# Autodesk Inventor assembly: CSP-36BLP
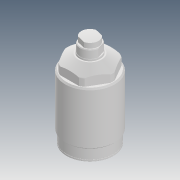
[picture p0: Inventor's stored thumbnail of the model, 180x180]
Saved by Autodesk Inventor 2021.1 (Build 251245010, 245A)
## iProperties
Created: 2019-01
Part Number: CSP-36BLP
Description: STEP AP203
Document SubType Name: Assembly
Designer: user
Title: CSP036BLP.STEP
Revision Number: ÈÎºÎ
Sending System: SolidWorks 2014
Preprocessor: SwSTEP 2.0
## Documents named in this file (4)
- D:\Vault_2016\Projekty\Clamptek\Hydraulic\CSP-P-K\CSP-36KP\Inventor\CSP-36BLP\CSP-36BLP.iam
- D:\Vault_2016\Projekty\Clamptek\Hydraulic\CSP-P-K\CSP-36KP\Inventor\CSP-36BLP\CSP-036-P±¾Ìå£¨³õÊ¼£©.ipt
- D:\Vault_2016\Projekty\Clamptek\Hydraulic\CSP-P-K\CSP-36KP\Inventor\CSP-36BLP\CSP-036»îÈû¸Ë.ipt
- D:\Vault_2016\Projekty\Clamptek\Hydraulic\CSP-P-K\CSP-36KP\Inventor\CSP-36BLP\CSP-036Ô²Í·ÂÝË¨.ipt
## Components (3 placed, 3 different names)
1. CSP-036-P±¾Ìå£¨³õÊ¼£©_1
2. CSP-036»îÈû¸Ë_2
3. CSP-036Ô²Í·ÂÝË¨_3
